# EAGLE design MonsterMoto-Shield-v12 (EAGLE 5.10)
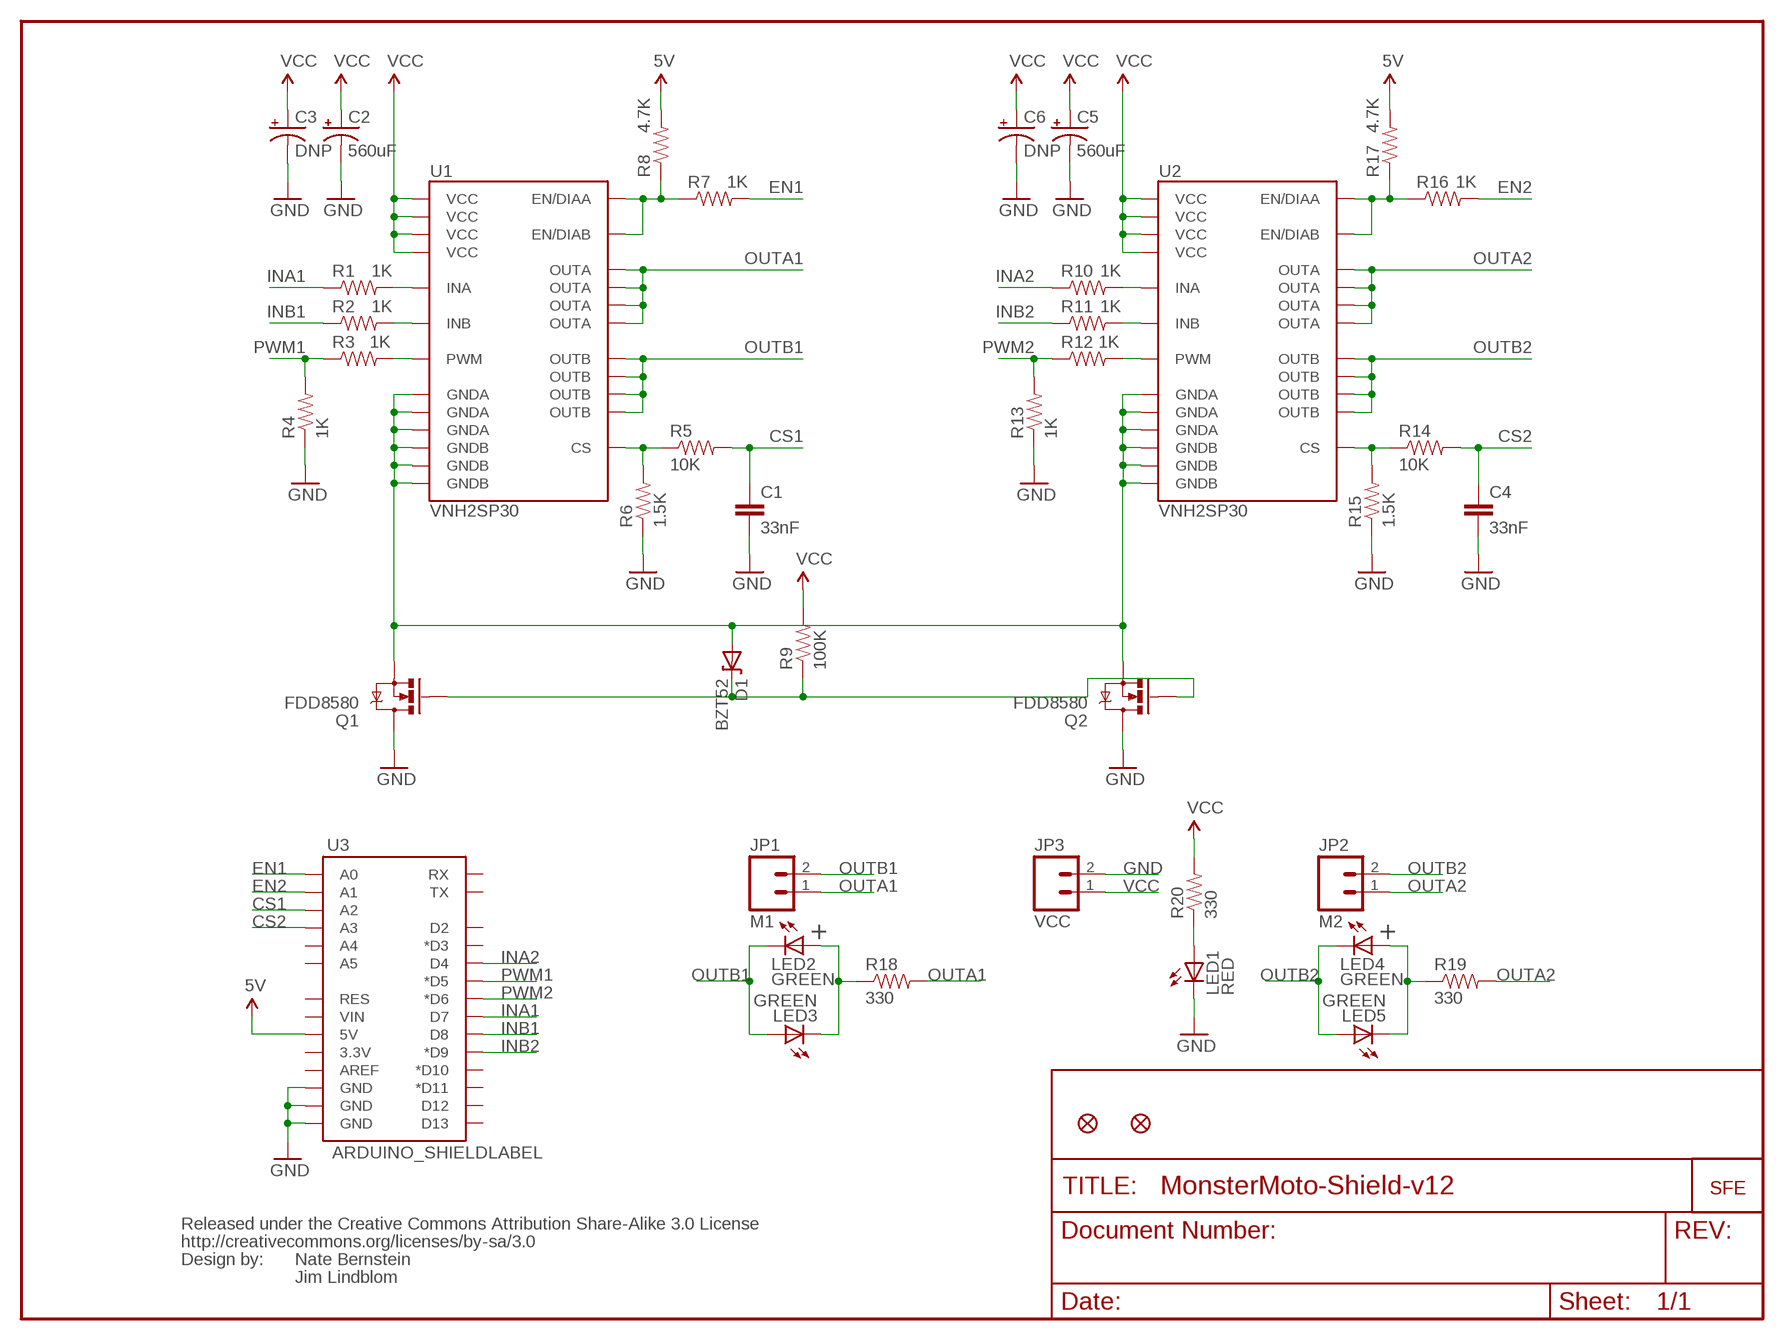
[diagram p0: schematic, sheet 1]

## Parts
C1  33nF  CAP0402-CAP  [0402-CAP]
C2  560uF  CAP_POLG  [PANASONIC_G]
C3  DNP  CAP_POLPTH4  [CPOL-RADIAL-1000UF-25V]
C4  33nF  CAP0402-CAP  [0402-CAP]
C5  560uF  CAP_POLG  [PANASONIC_G]
C6  DNP  CAP_POLPTH4  [CPOL-RADIAL-1000UF-25V]
D1  BZT52  DIODE-ZENER-BZT52  [SOD-323]
JP1  M1  M02PTH4  [1X02_XTRA_BIG]
JP2  M2  M02PTH4  [1X02_XTRA_BIG]
JP3  VCC  M02PTH4  [1X02_XTRA_BIG]
JP4  FIDUCIAL1X2  [FIDUCIAL-1X2]
JP5  LOGO-SFENEW  [SFE-NEW-WEBLOGO]
JP6  FIDUCIAL1X2  [FIDUCIAL-1X2]
LED1  RED  LED0603  [LED-0603]
LED2  GREEN  LED0603  [LED-0603]
LED3  GREEN  LED0603  [LED-0603]
LED4  GREEN  LED0603  [LED-0603]
LED5  GREEN  LED0603  [LED-0603]
Q1  FDD8580  MOSFET-NCHANNELFDD8580  [DPAK]
Q2  FDD8580  MOSFET-NCHANNELFDD8580  [DPAK]
R1  1K  RESISTOR0402-RES  [0402-RES]
R2  1K  RESISTOR0402-RES  [0402-RES]
R3  1K  RESISTOR0402-RES  [0402-RES]
R4  1K  RESISTOR0402-RES  [0402-RES]
R5  10K  RESISTOR0402-RES  [0402-RES]
R6  1.5K  RESISTOR0402-RES  [0402-RES]
R7  1K  RESISTOR0402-RES  [0402-RES]
R8  4.7K  RESISTOR0402-RES  [0402-RES]
R9  100K  RESISTOR0402-RES  [0402-RES]
R10  1K  RESISTOR0402-RES  [0402-RES]
R11  1K  RESISTOR0402-RES  [0402-RES]
R12  1K  RESISTOR0402-RES  [0402-RES]
R13  1K  RESISTOR0402-RES  [0402-RES]
R14  10K  RESISTOR0402-RES  [0402-RES]
R15  1.5K  RESISTOR0402-RES  [0402-RES]
R16  1K  RESISTOR0402-RES  [0402-RES]
R17  4.7K  RESISTOR0402-RES  [0402-RES]
R18  330  RESISTOR0402-RES  [0402-RES]
R19  330  RESISTOR0402-RES  [0402-RES]
R20  330  RESISTOR0402-RES  [0402-RES]
U1  VNH2SP30  [VNH2SP30]
U2  VNH2SP30  [VNH2SP30]
U3  ARDUINO_SHIELDLABEL  [DUEMILANOVE_SHIELD]
U$6  CREATIVE_COMMONS  [CREATIVE_COMMONS]

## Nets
5V: R8.2 R17.2 U3.5V
CS1: C1.1 R5.2 U3.A2
CS2: C4.1 R14.2 U3.A3
EN1: R7.2 U3.A0
EN2: R16.2 U3.A1
GND: C1.2 C2.- C3.2(-) C4.2 C5.- C6.2(-) JP3.2 LED1.C Q1.4(D) Q2.4(D) R4.1 R6.1 R13.1 R15.1 U3.GND@0(GND) U3.GND@1(GND) U3.GND@2(GND)
INA1: R1.1 U3.D7
INA2: R10.1 U3.D4
INB1: R2.1 U3.D8
INB2: R11.1 U3.D9(*D9)
N$1: R2.2 U1.11(INB)
N$2: R1.2 U1.5(INA)
N$3: R11.2 U2.11(INB)
N$4: R10.2 U2.5(INA)
N$5: R3.2 U1.8(PWM)
N$6: R12.2 U2.8(PWM)
N$7: R5.1 R6.2 U1.9(CS)
N$8: R14.1 R15.2 U2.9(CS)
N$9: R16.1 R17.1 U2.6(EN/DIAA) U2.10(EN/DIAB)
N$10: D1.2(A) Q1.3(S) Q2.3(S) U1.18(GNDB) U1.19(GNDB) U1.20(GNDB) U1.26(GNDA) U1.27(GNDA) U1.28(GNDA) U2.18(GNDB) U2.19(GNDB) U2.20(GNDB) U2.26(GNDA) U2.27(GNDA) U2.28(GNDA)
N$12: R7.1 R8.1 U1.6(EN/DIAA) U1.10(EN/DIAB)
N$13: D1.1(C) Q1.1(G) Q2.1(G) R9.1
N$14: LED2.A LED3.C R18.1
N$16: LED4.A LED5.C R19.1
N$18: LED1.A R20.1
OUTA1: JP1.1 R18.2 U1.1(OUTA) U1.25(OUTA) U1.30(OUTA) U1.SLUG3(OUTA)
OUTA2: JP2.1 R19.2 U2.1(OUTA) U2.25(OUTA) U2.30(OUTA) U2.SLUG3(OUTA)
OUTB1: JP1.2 LED2.C LED3.A U1.15(OUTB) U1.16(OUTB) U1.21(OUTB) U1.SLUG2(OUTB)
OUTB2: JP2.2 LED4.C LED5.A U2.15(OUTB) U2.16(OUTB) U2.21(OUTB) U2.SLUG2(OUTB)
PWM1: R3.1 R4.2 U3.D5(*D5)
PWM2: R12.1 R13.2 U3.D6(*D6)
VCC: C2.+ C3.1(+) C5.+ C6.1(+) JP3.1 R9.2 R20.2 U1.3(VCC) U1.13(VCC) U1.23(VCC) U1.SLUG1(VCC) U2.3(VCC) U2.13(VCC) U2.23(VCC) U2.SLUG1(VCC)
Unconnected: U3.3.3V U3.A4 U3.A5 U3.AREF U3.D2 U3.D3(*D3) U3.D10(*D10) U3.D11(*D11) U3.D12 U3.D13 U3.RES U3.RX U3.TX U3.VIN

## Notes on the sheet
- + | +
- Nate Bernstein
- Jim Lindblom

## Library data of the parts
C1 C4 = SparkFun:CAP: Capacitor
C2 C3 C5 C6 = SparkFun:CAP_POL: Capacitor Polarized
D1 = SparkFun:DIODE-ZENER: Zener Diode
JP1-JP3 = SparkFun:M02: Header 2
JP4 JP6 = SparkFun:FIDUCIAL: Fiducial Alignment Points
JP5 = SparkFun:LOGO-SFE: Spark Fun Electronics PCB Logo
LED1-LED5 = SparkFun:LED: LEDs
Q1 Q2 = SparkFun:MOSFET-NCHANNEL
R1-R20 = SparkFun:RESISTOR: Resistor
U1 U2 = SparkFun:VNH2SP30
U3 = SparkFun:ARDUINO_SHIELD
U$6 = SparkFun:CREATIVE_COMMONS

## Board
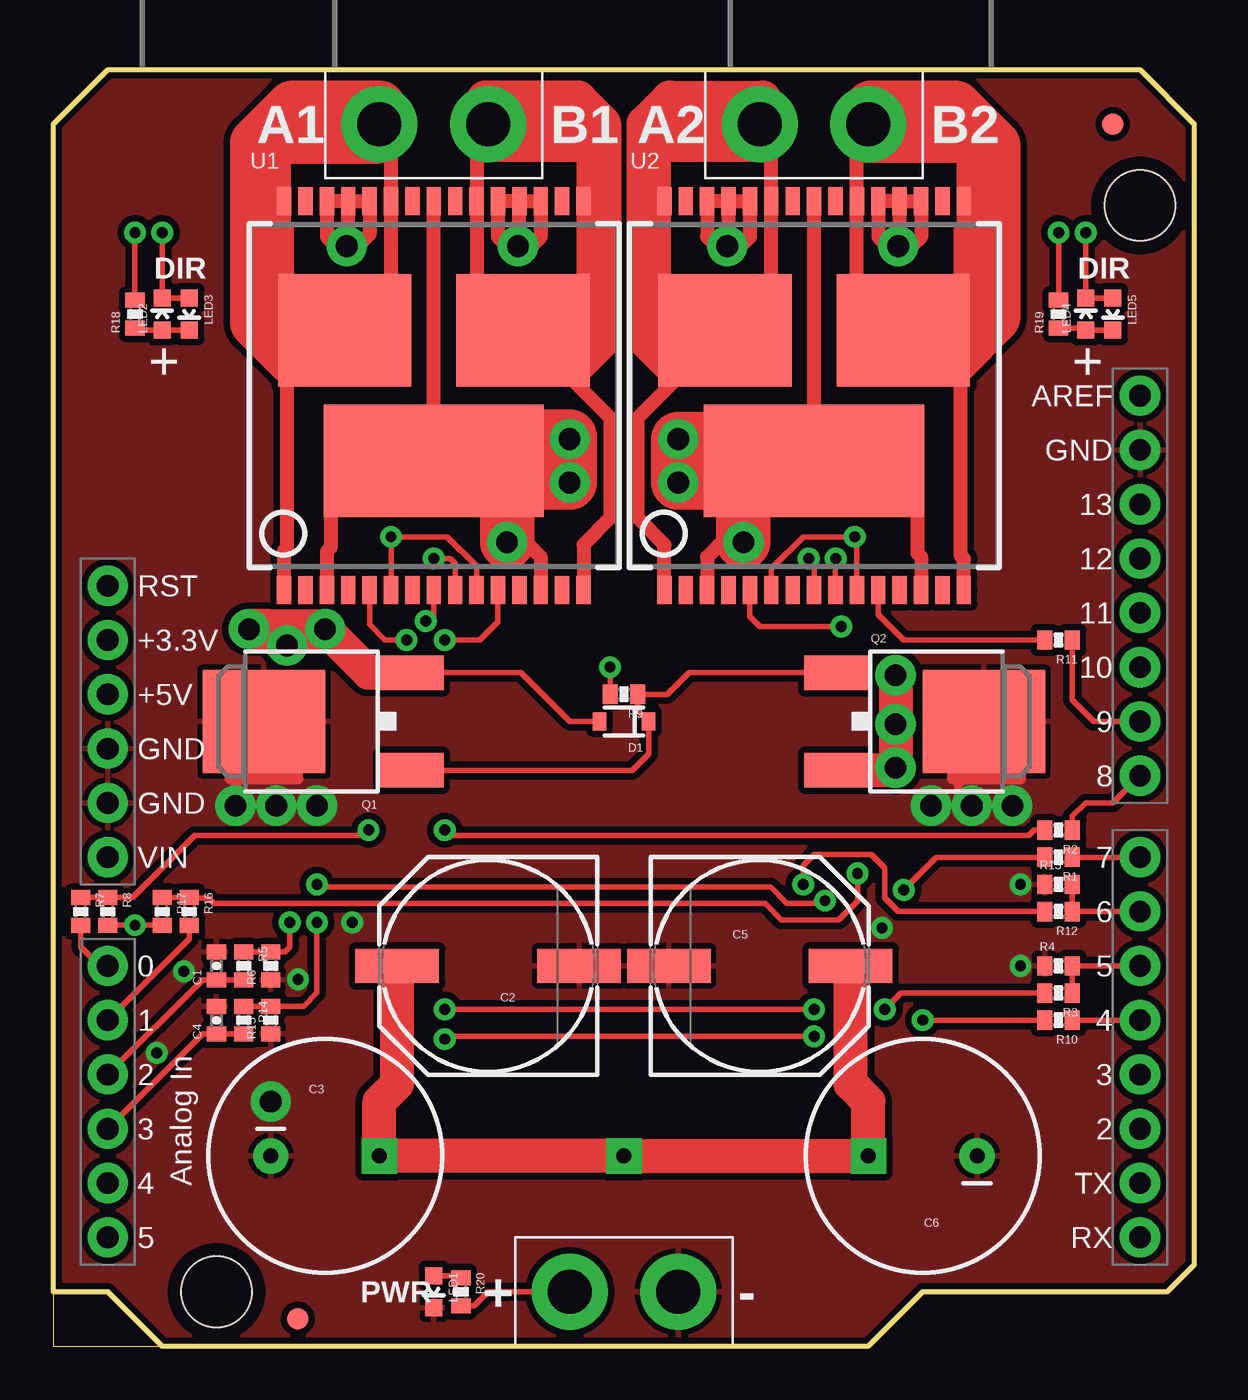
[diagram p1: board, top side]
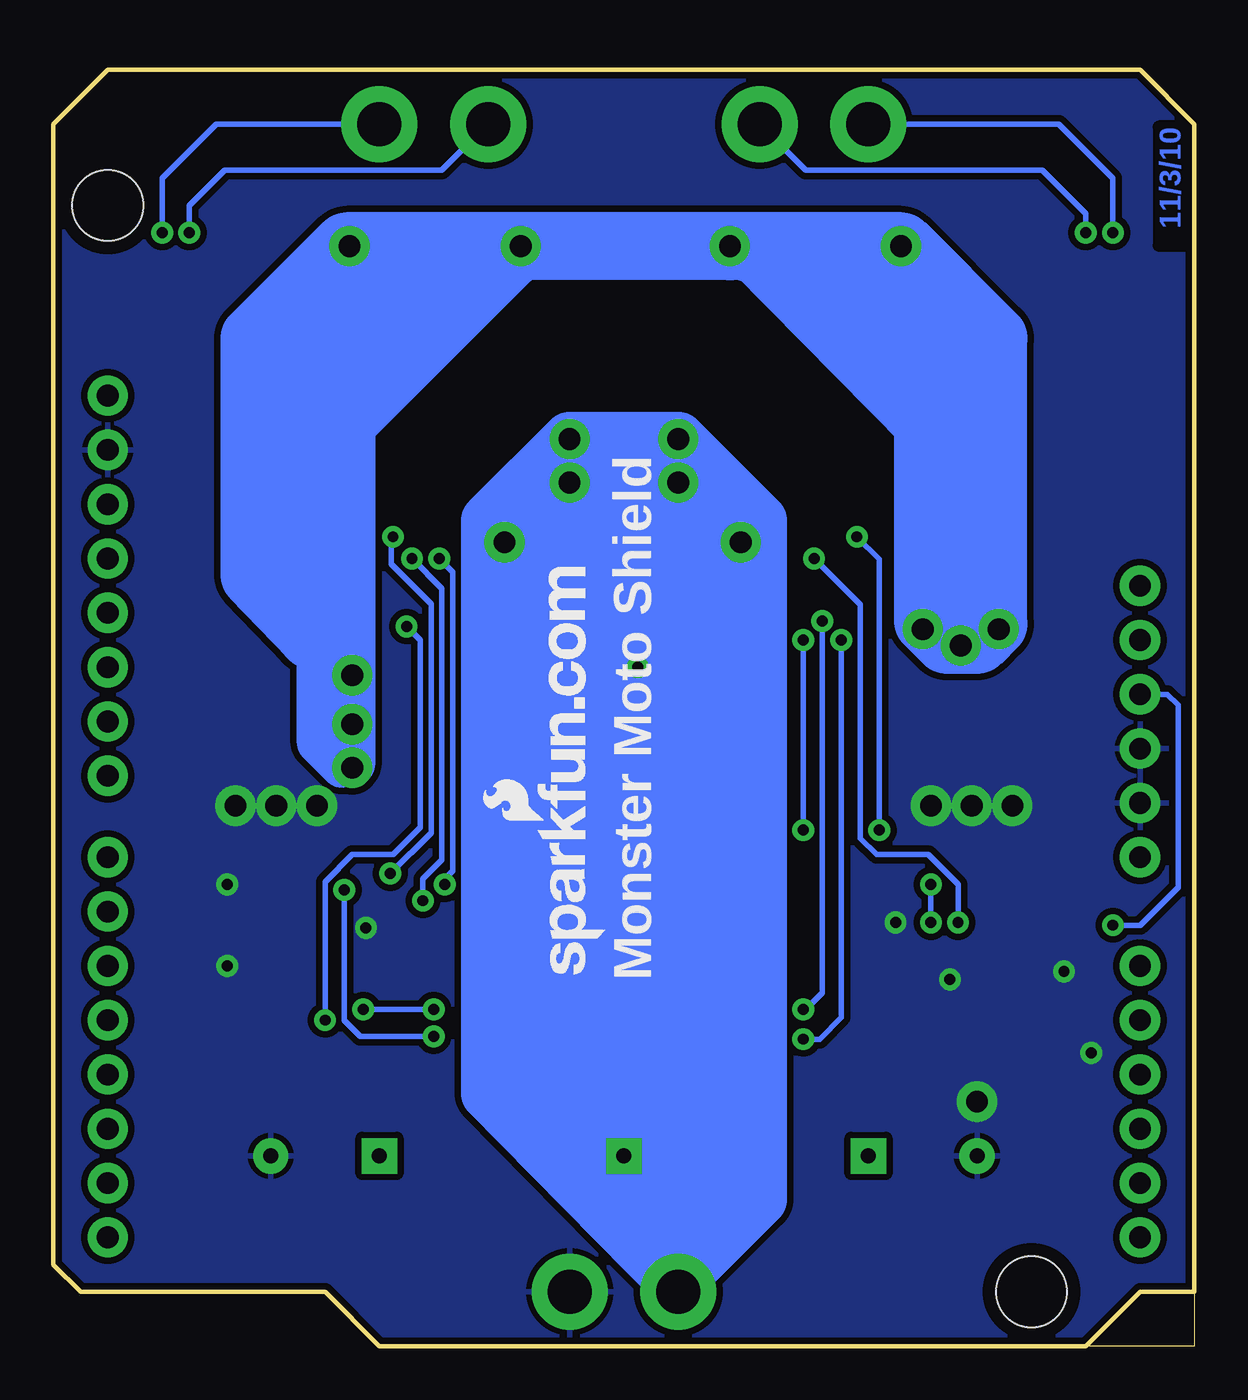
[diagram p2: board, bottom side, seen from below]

Size 53.34 x 59.69 mm. Coordinates in mm from the lower left corner, seen from the top.
Outline: 5.08,0 0,0 0,2.54
Outline: 0,2.54 2.54,2.54 5.08,0
Outline: 5.08,0 38.1,0 40.64,2.54 52.07,2.54 53.34,3.81 53.34,57.15 50.8,59.69 2.54,59.69 0,57.15 0,2.54
Copper layers (1*16): Top 0.035mm / dielectric 1.5mm / Bottom 0.035mm
Design rules "SparkFun *": minimum track width 8mil, minimum drill 20mil, track to track 8mil, track to pad 8mil, pad to pad 8mil, via to via 8mil, smd to smd 8mil, copper to edge 8mil, drill to drill 8mil, minimum pad ring 12mil, minimum via ring 10mil, stop-mask expansion 4mil, vias tented up to drill 40mil, thermal gap 10mil

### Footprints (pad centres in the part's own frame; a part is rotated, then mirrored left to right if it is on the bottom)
0402-CAP = smd 0.7 x 0.9: 1 -0.65,0; 2 0.65,0
PANASONIC_G = smd 3.9 x 1.6: + 4.25,0; - -4.25,0
CPOL-RADIAL-1000UF-25V = drill 0.7 pad 1.651 square: 1 2.54,0 | drill 0.7 pad 1.651 round: 2 -2.54,0
SOD-323 = smd 0.63 x 0.83: 1 -1.15,0; 2 1.15,0
1X02_XTRA_BIG = drill 2.057 pad 3.556 round: 1 -2.54,0; 2 2.54,0
FIDUCIAL-1X2 = smd 1 x 1: 1 0,0
LED-0603 = smd 0.8 x 0.8: A 0,-0.75; C 0,0.75
DPAK = smd 1.6 x 3: 1 -2.28,-5.31; 3 2.28,-5.31 | smd 4.826 x 5.715: 4 0,1.588
0402-RES = smd 0.7 x 0.9: 1 -0.65,0; 2 0.65,0
VNH2SP30 = smd 0.67 x 1.3: 1 -7,-9.1; 2 -6,-9.1; 3 -5,-9.1; 4 -4,-9.1; 5 -3,-9.1; 6 -2,-9.1; 7 -1,-9.1; 8 0,-9.1; 9 1,-9.1; 10 2,-9.1; 11 3,-9.1; 12 4,-9.1; 13 5,-9.1; 14 6,-9.1; 15 7,-9.1; 16 7,9.1; 17 6,9.1; 18 5,9.1; 19 4,9.1; 20 3,9.1; 21 2,9.1; 22 1,9.1; 23 0,9.1; 24 -1,9.1; 25 -2,9.1; 26 -3,9.1; 27 -4,9.1; 28 -5,9.1; 29 -6,9.1; 30 -7,9.1 | smd 10.3 x 5.25: SLUG1 0,-3.05 | smd 6.23 x 5.25: SLUG2 4.165,3.05; SLUG3 -4.165,3.05
DUEMILANOVE_SHIELD = drill 1.016 pad 1.88 round: 3.3V 50.8,26.67; 5V 50.8,29.21; A0 50.8,41.91; A1 50.8,44.45; A2 50.8,46.99; A3 50.8,49.53; A4 50.8,52.07; A5 50.8,54.61; AREF 2.54,15.24; D2 2.54,49.53; D3 2.54,46.99; D4 2.54,44.45; D5 2.54,41.91; D6 2.54,39.37; D7 2.54,36.83; D8 2.54,33.02; D9 2.54,30.48; D10 2.54,27.94; D11 2.54,25.4; D12 2.54,22.86; D13 2.54,20.32; GND@0 50.8,31.75; GND@1 50.8,34.29; GND@2 2.54,17.78; RES 50.8,24.13; RX 2.54,54.61; TX 2.54,52.07; VIN 50.8,36.83 | hole 3.302: 45.72,57.15; 2.54,6.35

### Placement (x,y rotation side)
C1  7.62,17.78 90 top
C2  20.32,17.78 180 top
C3  12.7,8.89 0 top
C4  7.62,15.24 90 top
C5  33.02,17.78 0 top
C6  40.64,8.89 180 top
D1  26.67,29.21 180 top
JP1  17.78,57.15 0 top
JP2  35.56,57.15 0 top
JP3  26.67,2.54 0 top
JP4  49.53,57.15 0 top
JP5  27.56,17.4 90 bottom
JP6  11.43,1.27 0 top
LED1  17.78,2.54 180 top
LED2  5.08,48.26 0 top
LED3  6.35,48.26 180 top
LED4  48.26,48.26 0 top
LED5  49.53,48.26 180 top
Q1  11.43,29.21 90 top
Q2  41.91,29.21 270 top
R1  46.99,22.86 180 top
R2  46.99,24.13 180 top
R3  46.99,16.51 180 top
R4  46.99,17.78 0 top
R5  8.89,17.78 270 top
R6  10.16,17.78 90 top
R7  1.27,20.32 270 top
R8  2.54,20.32 270 top
R9  26.67,30.48 180 top
R10  46.99,15.24 180 top
R11  46.99,33.02 180 top
R12  46.99,20.32 180 top
R13  46.99,21.59 0 top
R14  8.89,15.24 270 top
R15  10.16,15.24 90 top
R16  6.35,20.32 270 top
R17  5.08,20.32 270 top
R18  3.81,48.26 90 top
R19  46.99,48.26 90 top
R20  19.05,2.54 270 top
U1  17.78,44.45 0 top
U2  35.56,44.45 0 top
U3  53.34,59.69 180 top
U$6  not placed on the board

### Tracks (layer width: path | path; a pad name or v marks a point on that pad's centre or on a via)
5V  (via drill 0.51)
  Top 0.254: R8.2 2.56,19.68 v3.81,19.68 5.07,19.68 R17.2
  Bottom 0.254: U3.5V 1.27,30.48 0.76,29.97 0.76,21.45 R8.2 3.79,19.67 v3.81,19.68
CS1
  Top 0.254: R5.2 C1.1 6.97,17.13 U3.A2
CS2
  Top 0.254: R14.2 C4.1 6.97,14.59 U3.A3
EN1
  Top 0.254: R7.2 1.27,18.67 2.03,17.91 2.41,17.91 U3.A0
EN2
  Top 0.254: U3.A1 6.35,19.05 R16.2
GND  (via drill 0.51, 1.02 pad 1.88)
  Top 0.381: v8.51,25.27 8.51,26.29 8.89,26.54 | 42.29,25.27 42.29,26.29 42.67,26.54
  Top 0.508: 8.26,26.92 8.26,26.54 8.89,26.54 11.43,26.54 11.43,26.92 | 42.04,26.92 42.04,26.54 42.67,26.54 45.21,26.54 45.21,26.92
  other vias: 45.21,21.59 4.83,13.72 45.21,17.78 38.73,19.56 11.43,17.14 6.1,17.53 44.83,25.27 41.02,25.27 12.32,25.27 42.93,25.27 10.41,25.27 10.16,11.43 13.97,19.81
  pour Top (isolate 0.305): 0,2.54 0,57.15 2.54,59.69 50.8,59.69 53.34,57.15 53.34,3.81 52.07,2.54 40.64,2.54 38.1,0 5.08,0 2.54,2.54
  pour Bottom (isolate 0.305): 5.08,0 2.54,2.54 0,2.54 0,57.15 2.54,59.69 50.8,59.69 53.34,57.15 53.34,3.81 52.07,2.54 40.64,2.54 38.1,0
INA1
  Top 0.254: R1.1 U3.D7
INA2
  Top 0.254: R10.1 U3.D4
INB1
  Top 0.254: R2.1 47.64,24.78 48.26,25.4 49.53,25.4 U3.D8
INB2
  Top 0.254: U3.D9 48.64,29.21 47.64,30.21 R11.1
N$1  (via drill 0.51)
  Top 0.254: v18.29,33.02 19.94,33.02 20.78,33.86 U1.11 | v18.29,24.13 18.54,23.88 45.59,23.88 45.85,24.13 R2.2
  Bottom 0.254: v18.29,24.13 v18.29,33.02
N$2  (via drill 0.51)
  Top 0.254: v35.56,14.48 18.41,14.48 v18.29,14.35 | R1.2 41.27,22.86 v39.75,21.34 | U1.5 14.78,33.73 15.49,33.02 v16.51,33.02
  Bottom 0.254: v39.75,21.34 39.75,15.24 38.99,14.48 v35.56,14.48 | v18.29,14.35 17.53,14.35 16.51,15.37 v16.51,33.02
N$3
  Top 0.254: U2.11 38.56,34.21 39.75,33.02 R11.2
N$4  (via drill 0.51)
  Top 0.254: v40.64,15.24 R10.2 | U2.5 32.56,34.12 33.02,33.66 v36.83,33.66
  Bottom 0.254: v40.64,15.24 40.64,21.72 39.37,22.99 37.47,22.99 36.2,24.26 36.2,33.02 v36.83,33.66
N$5  (via drill 0.51)
  Top 0.254: U1.8 17.78,33.91 v17.4,33.91 | v18.29,15.75 v35.56,15.75 | R3.2 39.62,16.51 v38.86,15.75
  Bottom 0.254: v35.56,15.75 v38.86,15.75 | v18.29,15.75 18.16,15.75 17.4,16.51 v17.4,33.91
N$6  (via drill 0.51)
  Top 0.254: U2.8 35.56,36.58 v35.31,36.83 | R12.2 39.5,20.32 38.86,20.95 38.86,22.35 38.23,22.99 35.56,22.99 35.05,22.48 v35.05,21.59
  Bottom 0.254: v35.05,21.59 35.05,21.84 34.67,22.23 34.67,36.2 v35.31,36.83
N$7  (via drill 0.51)
  Top 0.254: R5.1 R6.2 10.81,18.43 11.05,18.67 v11.05,19.81 | U1.9 18.78,36.59 18.54,36.83 v17.78,36.83
  Bottom 0.254: v11.05,19.81 11.05,21.59 12.45,22.99 14.86,22.99 15.62,23.75 15.62,34.67 v17.78,36.83
N$8  (via drill 0.51)
  Top 0.254: R14.1 R15.2 11.7,15.89 12.32,16.51 v12.32,19.81 | U2.9 36.56,36.81 v36.58,36.83 | v12.32,21.59 12.45,21.46 33.53,21.46 34.29,20.7 35.94,20.7 v36.07,20.83
  Bottom 0.254: v12.32,19.81 v12.32,21.59 | v36.58,36.83 35.18,35.43 35.18,22.73 36.07,21.84 v36.07,20.83
N$9  (via drill 0.51)
  Top 0.254: R17.1 R16.1 6.37,20.95 7.24,20.95 7.49,20.7 33.27,20.7 34.04,19.94 36.7,19.94 37.59,20.83 v37.59,22.1 | U2.10 37.56,37.75 v37.47,37.85 35.05,37.85 33.56,36.35 U2.6
  Bottom 0.254: v37.59,22.1 35.69,24 35.69,34.7 37.56,36.58 37.56,37.75 v37.47,37.85
N$10  (via drill 1.02 pad 1.88)
  Top 0.254: Q1.3 21.85,31.49 24.13,29.21 D1.2
  Top 0.645: U2.19 U2.18 40.56,51.86 40.13,51.44 | U2.19 U2.20 38.56,51.86 38.99,51.44 | U1.27 U1.28 12.78,52.07 12.78,51.86 13.21,51.44 | U1.19 U1.20 20.78,51.86 21.21,51.44 | U1.19 U1.18 22.78,51.86 22.35,51.44 | U2.27 U2.28 30.56,51.86 30.99,51.44 | U1.19 21.78,51.5 v21.72,51.44 | U1.27 13.78,51.5 v13.72,51.44 | U2.19 39.56,51.5 v39.5,51.44 | U1.27 U1.26 14.78,51.99 14.22,51.44 | U2.27 U2.26 32.56,51.86 | 31.56,51.5 U2.27 | v31.5,51.44 31.56,51.5 | 31.56,51.5 32.2,51.5 | 32.2,51.5 32.51,51.82 | 32.2,51.5 31.94,51.5
  Top 1.6: Q1.3 14.74,31.49 v12.7,33.53 | Q2.3 39.25,26.93 v39.37,27.05 v39.37,31.37
  Top 1.88: v12.7,33.53 v9.14,33.53 10.16,33.53 v10.92,32.77
  Bottom 0.254: 11.05,43.56 11.05,38.48 11.43,38.1 12.32,38.1 12.45,43.18
  Bottom 0.645: 32,51.18 32,51.05 | 32,51.31 31.62,51.31 v31.5,51.44
  Bottom 1.6: 41.66,39.88 41.66,35.81 | v39.37,29.08 40.89,29.08 41.02,29.21 | v39.37,31.37 39.5,31.37 39.88,31.75 | 41.66,39.88 41.66,44.2 | 41.66,39.88 40.39,39.88 39.88,43.18
  Bottom 1.88: v9.14,33.53 9.4,33.78 | v39.37,31.37 39.24,31.37 39.24,27.18 v39.37,27.05 39.88,27.05 41.02,28.19 41.02,29.21 41.02,32.26
  Bottom 3.175: 20.7,51.31 20.45,51.31 12.45,43.18 12.45,33.91 11.56,33.02 10.16,33.02 9.4,33.78 9.4,47.12 v13.72,51.44 v21.72,51.44 v31.5,51.44 v39.5,51.44 39.62,51.44 43.94,47.12 43.94,36.07 41.27,33.27 | 39.88,31.5 39.88,31.75 39.88,43.18 32,51.05 31.75,51.31 | 32,51.31 32,51.18
  Bottom 5.08: 11.05,43.56 17.27,49.78 | 41.66,44.2 36.83,49.02
N$12  (via drill 0.51)
  Top 0.254: U1.10 19.78,36.48 18.41,37.85 v15.78,37.85 U1.6 | R7.1 R8.1 3.7,20.97 6.6,23.88 14.48,23.88 v14.73,24.13
  Bottom 0.254: v14.73,24.13 14.73,36.8 v15.78,37.85
N$13
  Top 0.254: Q1.1 27.06,26.93 27.82,27.69 D1.1 27.32,29.71 R9.1 28.7,30.48 29.71,31.49 Q2.1
N$14
  Top 0.254: LED3.C LED2.A 3.91,47.51 R18.1
N$16
  Top 0.254: LED5.C LED4.A 48.16,47.61 R19.1
N$18
  Top 0.254: LED1.A 18.95,3.29 R20.1
OUTA1  (via drill 0.51)
  Top 0.254: JP1.1 14.73,57.15 | v3.81,52.07 R18.2
  Top 0.61: 10.92,46.48 11.43,46.99 13.11,46.99 U1.SLUG3 15.78,49.66
  Top 0.645: U1.1 10.78,37.2 10.92,37.34 10.92,45.72 10.92,46.48 | 15.78,49.66 U1.25 15.78,56.61 JP1.1 | 11.43,46.99 10.92,47.5 10.92,52.2 10.78,52.34 U1.30 10.78,56.66 10.67,56.77 | 10.79,46.35 11.18,46.23 | 10.67,46.1 11.05,46.1 | 10.79,55.75 10.92,55.88 10.29,55.88 10.16,56.01 | 10.03,56.01 9.4,56.01 9.53,56.26
  Top 0.762: 11.43,46.99 10.79,46.35 | 10.67,46.1 10.16,46.61 10.16,49.15 10.54,49.15
  Top 1.143: 10.03,56.01 10.16,56.01 | 10.67,46.1 10.67,45.97 10.92,45.72
  Top 1.397: 10.16,56.01 15.24,56.01
  Top 2.032: 14.73,57.15 11.81,57.15
  Top 2.54: 11.18,46.23 9.53,47.88 9.53,56.26 11.18,57.91 15.24,57.91
  Top 3.81: 13.36,47.75 U1.SLUG3
  Bottom 0.254: v3.81,52.07 3.81,54.61 6.35,57.15 JP1.1
OUTA2  (via drill 0.51)
  Top 0.254: 27.69,57.15 28.19,56.64 | JP2.1 33.15,57.15 33.4,56.9 | 27.69,49.02 27.81,48.39 30.05,46.15 | v46.99,52.07 R19.2
  Top 0.645: U2.1 28.56,37.48 27.3,38.73 27.3,43.41 30.05,46.15 U2.SLUG3 | U2.SLUG3 28.7,49.81 28.7,49.66 28.56,49.8 U2.30 28.56,55.87 28.57,55.88 | U2.SLUG3 33.56,49.66 U2.25 33.56,56.23 33.27,56.52
  Top 0.671: 33.4,56.9 33.53,56.77
  Top 1.143: 27.69,49.02 29.08,47.37
  Top 1.168: 27.94,47.5 28.19,47.24 27.69,47.12
  Top 1.778: 33.15,58.29 28.83,58.29 27.69,57.15 27.69,49.02 27.69,47.12 28.83,45.97
  Top 2.54: 28.19,56.64 33.15,56.64 33.4,56.9
  Bottom 0.254: v46.99,52.07 46.99,53.34 45.34,54.99 35.18,54.99 JP2.1
OUTB1  (via drill 0.51)
  Top 0.254: LED3.A LED2.C v5.08,52.07 | 25.15,56.64 25.65,57.15
  Top 0.61: 22.66,46.79 U1.SLUG2 19.78,49.66
  Top 0.645: U1.15 24.78,37.48 26.04,38.73 26.04,43.41 22.66,46.79 24.64,48.77 24.64,49.66 24.78,49.8 U1.16 | 19.78,49.66 U1.21 19.78,56.61 20.13,56.96 JP1.2
  Top 0.671: U1.16 24.78,56.5 24.13,57.15
  Top 1.143: 25.65,49.02 24.51,47.62
  Top 1.168: 25.65,47.12 25.59,47.05 25.15,47.24 25.02,47.24 | 25.02,47.24 24.89,47.24 | 25.02,47.24 25.15,47.37
  Top 1.778: 20.19,58.29 24.51,58.29 25.65,57.15 25.65,49.02 25.65,47.12 | 25.59,47.05 24.51,45.97
  Top 2.54: 25.15,56.64 20.45,56.64 20.13,56.96 19.94,57.15
  Bottom 0.254: JP1.2 18.16,54.99 7.11,54.99 5.08,52.96 v5.08,52.07
OUTB2  (via drill 0.51)
  Top 0.254: LED5.A LED4.C v48.26,52.07 | 42.42,46.48 42.42,46.99 42.16,47.24 | 42.16,47.24 41.91,47.5 | 42.16,47.24 42.42,47.5 | 42.16,47.24 41.91,46.99
  Top 0.645: U2.15 42.56,36.81 42.42,36.96 42.42,45.72 42.16,45.97 | U2.SLUG2 37.56,49.66 U2.21 37.56,56.61 JP2.2 | 42.42,47.5 42.42,52.2 42.56,52.34 U2.16 42.56,56.37 42.16,56.26
  Top 0.762: 43.43,49.15 42.93,49.15 42.93,48.26 | 42.93,48.26 42.93,48.01 | U2.SLUG2 41.4,47.5 41.91,46.99 | 42.42,47.5 42.42,47.75 42.93,48.26 | 42.04,46.23 42.42,46.48
  Top 1.88: 42.16,45.97 42.04,46.23 | 42.16,56.26 38.1,56.26 38.1,56.64
  Top 2.54: 42.04,46.23 43.94,48.13 43.94,56.13 42.16,57.91 38.23,57.91
  Top 3.81: U2.SLUG2
  Bottom 0.254: v48.26,52.07 48.26,54.61 45.72,57.15 JP2.2
PWM1
  Top 0.254: R3.1 R4.2 U3.D5
PWM2
  Top 0.254: R13.2 R12.1 U3.D6
VCC  (via drill 0.51, 0.7 pad 1.65, 1.02 pad 1.88)
  Top 0.254: R20.2 19.67,1.89 20.32,2.54 JP3.1 | v26.02,31.75 R9.2
  Top 0.61: 22.86,40.39 22.78,40.31 | 12.95,39.62 13.97,40.64 17.78,40.64 | 20.32,42.55 21.27,41.59 22.61,40.26 | 40.39,39.62 39.37,40.64 35.56,40.64
  Top 0.645: U1.3 12.78,37.16 12.95,37.34 12.95,39.62 | U2.13 40.56,36.91 40.39,37.08 40.39,39.62 | 17.78,40.64 U1.23 | 35.56,40.64 U2.SLUG1 U2.23 | v24.13,42.42 24.13,42.55 | U1.13 22.78,36.91 22.1,37.59 v21.21,37.59 | U2.3 30.56,36.91 31.24,37.59 31.75,37.59 32.26,38.1
  Top 1.6: C2.+ 16.07,12.26 15.24,11.43 C3.1 v26.67,8.89 C6.1 38.1,11.43 37.27,12.26 C5.+
  Top 2.54: v24.13,40.39 24.13,41.91 | v24.13,40.39 22.86,40.39 18.79,40.39 U1.SLUG1 | v24.13,42.42 v24.13,40.39 | 24.13,42.55 20.32,42.55 19.68,42.55 17.78,40.64 | 31.75,42.42 v29.21,42.42 v29.21,40.39 31.75,40.39 | 31.75,42.42 33.78,42.42 35.56,40.64 | v21.21,37.59 21.21,41.53 21.27,41.59 | v32.26,37.59 32.26,38.1 32.26,41.91 31.75,42.42
  Bottom 0.254: 24.13,40.64 v24.13,40.39 24.38,40.39 | 20.32,6.86 20.32,6.99
  Bottom 0.508: 21.59,10.03 21.72,10.03 | 21.59,10.03 21.46,10.03 | 20.32,6.99 20.32,8.76 21.59,10.03 | 26.67,10.16 v26.67,8.89
  Bottom 0.645: v26.02,31.75 26.42,31.75 26.67,32
  Bottom 1.6: 24.13,3.05 24.13,7.62
  Bottom 11.43: 26.67,12.7 26.67,32 26.67,36.83
  Bottom 2.54: JP3.1 24.13,2.79 | 20.32,6.86 24.13,3.05 24.13,2.79 | 24.13,2.79 33.02,11.81 33.02,38.61 | 24.38,40.39 23.88,40.39 | 20.32,6.99 20.32,38.61 v24.13,42.42 | v24.13,42.42 v29.21,42.42 | v24.13,42.42 v29.21,42.42 | v29.21,42.42 32.89,38.73
  Bottom 6.452: 26.67,10.16 26.67,12.7
  Bottom 6.858: 24.13,7.62 26.67,10.16

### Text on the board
Bottom: 11/3/10
tPlace: A1 | A2 | B1 | B2 | DIR | DIR | + | + | PWR | + | -
bPlace: Monster Moto Shield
